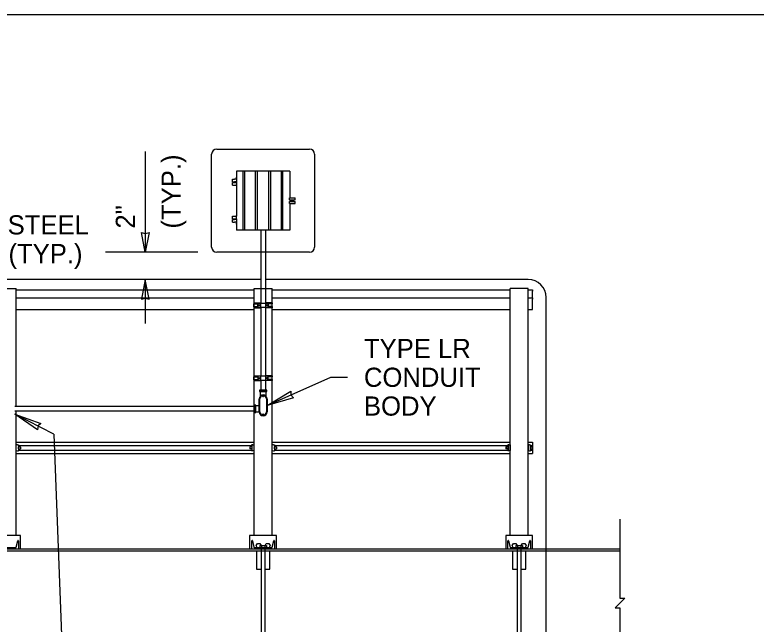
# Model space of a CAD drawing. Extents: x 99862 to 103680, y 99470 to 105076.
# Drawn here: x 101141 to 101760, y 101567 to 102076 of the extents above; entities that cross this region are included whole.
import ezdxf

# ---------------------------------------------------------------- set-up
doc = ezdxf.new("R2010")
doc.units = 0
for name, color, linetype in [('Level 1', 7, 'Continuous'), ('Level 10', 7, 'Continuous'), ('Level 12', 7, 'Continuous'), ('Level 15', 7, 'Continuous'), ('Level 16', 7, 'Continuous'), ('Level 18', 7, 'Continuous'), ('Level 19', 7, 'Continuous'), ('Level 2', 7, 'Continuous'), ('Level 20', 7, 'Continuous'), ('Level 27', 7, 'Continuous'), ('Level 4', 7, 'Continuous'), ('Level 5', 7, 'Continuous'), ('Level 9', 7, 'Continuous')]:
    doc.layers.add(name, color=color, linetype=linetype)

msp = doc.modelspace()

# ---------------------------------------------------------------- linework, layer by layer
at = {"layer": 'Level 1'}
for p, q in [((101346.66, 101854.73), (100923.17, 101854.73)), ((101569.75, 101854.73), (101350.49, 101854.73)), ((101584.75, 101329.97), (101584.75, 101839.73))]:
    msp.add_line(p, q, dxfattribs=at)
msp.add_lwpolyline([(99862, 99999.5), (103151, 99999.5), (103151, 102075.5), (99862, 102075.5)], close=True, dxfattribs=at)
msp.add_arc((101569.75, 101839.73), 15, 0, 90, dxfattribs=at)
at = {"layer": 'Level 10'}
for p, q in [((101146.16, 101641.07), (101123.67, 101641.07)), ((101146.16, 101629.82), (101146.16, 101641.07)), ((101337.33, 101641.07), (101337.33, 101629.82)), ((101359.82, 101641.07), (101337.33, 101641.07)), ((101359.82, 101629.82), (101359.82, 101641.07)), ((101551.02, 101641.07), (101551.02, 101629.82)), ((101573.51, 101641.07), (101551.02, 101641.07)), ((101573.51, 101629.82), (101573.51, 101641.07)), ((101142.55, 101631.42), (101143.73, 101636.65)), ((101144.29, 101636.58), (101144.29, 101629.82)), ((101339.21, 101629.82), (101339.21, 101636.58)), ((101339.76, 101636.65), (101340.94, 101631.42)), ((101356.21, 101631.42), (101357.39, 101636.65)), ((101357.95, 101636.58), (101357.95, 101629.82)), ((101552.89, 101629.82), (101552.89, 101636.58)), ((101553.44, 101636.65), (101554.63, 101631.42)), ((101569.89, 101631.42), (101571.08, 101636.65)), ((101571.63, 101636.58), (101571.63, 101629.82)), ((101144.29, 101629.82), (101125.55, 101629.82)), ((101127.81, 101630.99), (101142.02, 101630.99)), ((101357.95, 101629.82), (101339.21, 101629.82)), ((101341.47, 101630.99), (101355.68, 101630.99)), ((101571.63, 101629.82), (101552.89, 101629.82)), ((101555.16, 101630.99), (101569.36, 101630.99)), ((101349.98, 101612.95), (101354.2, 101612.95)), ((101563.67, 101612.95), (101567.88, 101612.95))]:
    msp.add_line(p, q, dxfattribs=at)
for points in [[(101347.17, 101627.95), (101342.95, 101627.95), (101342.95, 101612.95), (101347.17, 101612.95)], [(101354.2, 101612.95), (101354.2, 101627.95), (101349.98, 101627.95)], [(101560.85, 101627.95), (101556.64, 101627.95), (101556.64, 101612.95), (101560.85, 101612.95)], [(101567.88, 101612.95), (101567.88, 101627.95), (101563.67, 101627.95)]]:
    msp.add_lwpolyline(points, dxfattribs=at)
for centre, radius, start, end in [((101144.01, 101636.58), 0.281, 0, 167.26097), ((101339.49, 101636.58), 0.281, 12.73903, 180), ((101357.67, 101636.58), 0.281, 0, 167.26097), ((101553.17, 101636.58), 0.281, 12.73903, 180), ((101571.35, 101636.58), 0.281, 0, 167.26097), ((101142.02, 101631.54), 0.544, 270, 347.26097), ((101341.47, 101631.54), 0.544, 192.73903, 270), ((101355.68, 101631.54), 0.544, 270, 347.26097), ((101555.16, 101631.54), 0.544, 192.73903, 270), ((101569.36, 101631.54), 0.544, 270, 347.26097)]:
    msp.add_arc(centre, radius, start, end, dxfattribs=at)
at = {"layer": 'Level 12'}
for p, q in [((101646.35, 101629.82), (100274.6, 101629.82)), ((101646.35, 101627.95), (100276.47, 101627.95))]:
    msp.add_line(p, q, dxfattribs=at)
at = {"layer": 'Level 15'}
for p, q in [((101250.23, 101961.42), (101250.23, 101877.45)), ((101294.13, 101877.45), (101217.08, 101877.45)), ((101250.23, 101854.73), (101250.23, 101818.04)), ((101173.95, 101725.61), (101141.32, 101742.4))]:
    msp.add_line(p, q, dxfattribs=at)
for points in [[(101250.23, 101877.45), (101247.02, 101893.82), (101250.23, 101893.07), (101253.44, 101893.82)], [(101250.23, 101854.73), (101247.02, 101838.36), (101250.23, 101839.12), (101253.44, 101838.36)], [(101351.86, 101749.6), (101371.59, 101761.47), (101371.82, 101758.32), (101373.98, 101756)], [(101141.32, 101742.4), (101163.01, 101734.66), (101160.71, 101732.48), (101160.29, 101729.34)]]:
    msp.add_lwpolyline(points, close=True, dxfattribs=at)
for points in [[(101351.86, 101749.6), (101405, 101773.11), (101419, 101773.11)], [(101173.95, 101725.61), (101193.42, 101215.78), (101209.42, 101215.78)], [(101646.35, 101654.6), (101646.35, 101588.89), (101650.39, 101588.89), (101642.32, 101580.82), (101646.35, 101580.82), (101646.35, 101515.1)]]:
    msp.add_lwpolyline(points, dxfattribs=at)
at = {"layer": 'Level 16'}
for p, q in [((101309.88, 101963.43), (101387.27, 101963.43)), ((101305.59, 101881.75), (101305.59, 101959.13)), ((101391.57, 101959.13), (101391.57, 101881.75)), ((101387.27, 101877.45), (101309.88, 101877.45))]:
    msp.add_line(p, q, dxfattribs=at)
for centre, start, end in [((101309.88, 101959.13), 90, 180), ((101387.27, 101959.13), 0, 90), ((101309.88, 101881.75), 180, 270), ((101387.27, 101881.75), 270, 0)]:
    msp.add_arc(centre, 4.3, start, end, dxfattribs=at)
at = {"layer": 'Level 18'}
for p, q in [((101346.66, 101895.74), (101346.66, 101834.89)), ((101350.49, 101895.74), (101350.49, 101834.89)), ((101346.66, 101831.43), (101346.66, 101774.02)), ((101350.49, 101831.43), (101350.49, 101774.02)), ((101346.66, 101770.56), (101346.66, 101762.27)), ((101350.49, 101770.56), (101350.49, 101762.27)), ((101346.12, 101761.18), (101346.12, 101757.24)), ((101346.58, 101761.18), (101346.58, 101762.27)), ((101347.58, 101761.18), (101347.58, 101762.27)), ((101348.58, 101761.18), (101348.58, 101762.27)), ((101349.58, 101761.18), (101349.58, 101762.27)), ((101350.59, 101761.18), (101350.59, 101762.27)), ((101351.04, 101757.24), (101351.04, 101761.18)), ((101345.3, 101744.14), (101345.3, 101755.07)), ((101351.86, 101755.07), (101351.86, 101744.14)), ((101341.38, 101748.68), (101141.32, 101748.68)), ((101342.47, 101748.79), (101341.38, 101748.79)), ((101342.47, 101747.79), (101341.38, 101747.79)), ((101342.47, 101746.79), (101341.38, 101746.79)), ((101342.47, 101745.78), (101341.38, 101745.78)), ((101345.3, 101749.25), (101342.47, 101749.25)), ((101341.38, 101744.85), (101141.32, 101744.85)), ((101342.47, 101744.78), (101341.38, 101744.78)), ((101342.47, 101744.33), (101345.3, 101744.33))]:
    msp.add_line(p, q, dxfattribs=at)
for points in [[(101351.59, 101762.27), (101345.58, 101762.27), (101345.58, 101761.18), (101351.59, 101761.18)], [(101341.38, 101749.79), (101341.38, 101743.78), (101342.47, 101743.78), (101342.47, 101749.79)]]:
    msp.add_lwpolyline(points, close=True, dxfattribs=at)
for centre, start, end in [((101348.58, 101755.07), 0, 180), ((101348.58, 101744.14), 180, 0)]:
    msp.add_arc(centre, 3.28, start, end, dxfattribs=at)
at = {"layer": 'Level 19'}
for p, q in [((101142.44, 101846.04), (101341.08, 101846.04)), ((101356.07, 101846.04), (101554.74, 101846.04)), ((101569.73, 101846.04), (101573.51, 101846.04)), ((101573.51, 101846.04), (101573.51, 101844.93)), ((101573.51, 101839.5), (101573.51, 101844.93)), ((101142.44, 101839.5), (101341.08, 101839.5)), ((101356.07, 101839.5), (101554.74, 101839.5)), ((101569.73, 101839.5), (101573.51, 101839.5)), ((101573.51, 101839.5), (101573.51, 101838.34)), ((101573.51, 101829.67), (101573.51, 101838.34)), ((101142.44, 101829.67), (101341.08, 101829.67)), ((101356.07, 101829.67), (101554.74, 101829.67)), ((101569.73, 101829.67), (101573.51, 101829.67)), ((101143.48, 101716.86), (101142.41, 101716.69)), ((101142.44, 101718.86), (101341.08, 101718.86)), ((101143.48, 101716.86), (101144.15, 101716.86)), ((101144.15, 101716.86), (101144.48, 101716.86)), ((101144.23, 101715.03), (101144.23, 101713.53)), ((101144.23, 101715.03), (101145.73, 101715.03)), ((101144.48, 101716.86), (101144.48, 101715.03)), ((101144.48, 101716.86), (101144.5, 101716.86)), ((101144.53, 101716.04), (101339.01, 101716.04)), ((101145.73, 101715.03), (101145.94, 101715.03)), ((101145.94, 101714.92), (101145.94, 101715.03)), ((101145.94, 101714.92), (101145.94, 101713.53)), ((101337.55, 101715.03), (101337.55, 101714.92)), ((101337.76, 101715.03), (101337.55, 101715.03)), ((101337.55, 101714.92), (101337.55, 101713.53)), ((101339.26, 101715.03), (101337.76, 101715.03)), ((101339.01, 101716.86), (101339, 101716.86)), ((101339.01, 101716.86), (101339.01, 101715.03)), ((101339.35, 101716.86), (101339.01, 101716.86)), ((101339.26, 101715.03), (101339.26, 101713.53)), ((101340.01, 101716.86), (101339.35, 101716.86)), ((101340.01, 101716.86), (101341.08, 101716.69)), ((101356.07, 101718.86), (101554.74, 101718.86)), ((101357.14, 101716.86), (101356.07, 101716.69)), ((101357.14, 101716.86), (101357.81, 101716.86)), ((101357.81, 101716.86), (101358.14, 101716.86)), ((101357.89, 101715.03), (101357.89, 101713.53)), ((101357.89, 101715.03), (101359.39, 101715.03)), ((101358.14, 101716.86), (101358.14, 101715.03)), ((101358.14, 101716.86), (101358.16, 101716.86)), ((101358.14, 101716.04), (101552.69, 101716.04)), ((101359.39, 101715.03), (101359.6, 101715.03)), ((101359.6, 101714.92), (101359.6, 101715.03)), ((101359.6, 101714.92), (101359.6, 101713.53)), ((101551.45, 101715.03), (101551.23, 101715.03)), ((101551.23, 101714.92), (101551.23, 101713.53)), ((101551.24, 101715.03), (101551.24, 101714.92)), ((101551.45, 101715.03), (101551.45, 101713.53)), ((101552.95, 101715.03), (101551.45, 101715.03)), ((101552.69, 101716.86), (101552.68, 101716.86)), ((101552.69, 101716.86), (101552.69, 101715.03)), ((101553.03, 101716.86), (101552.69, 101716.86)), ((101552.95, 101715.03), (101552.95, 101713.53)), ((101553.03, 101716.86), (101553.03, 101711.71)), ((101553.69, 101716.86), (101553.03, 101716.86)), ((101553.69, 101716.86), (101554.77, 101716.69)), ((101554.77, 101716.69), (101554.77, 101711.88)), ((101569.73, 101718.86), (101573.51, 101718.86)), ((101569.75, 101716.69), (101569.73, 101716.69)), ((101570.83, 101716.86), (101569.75, 101716.69)), ((101569.75, 101716.69), (101569.75, 101711.88)), ((101570.83, 101716.86), (101571.49, 101716.86)), ((101571.49, 101716.86), (101571.49, 101711.71)), ((101571.49, 101716.86), (101571.83, 101716.86)), ((101571.57, 101715.03), (101573.07, 101715.03)), ((101571.57, 101715.03), (101571.57, 101713.53)), ((101571.83, 101716.86), (101571.84, 101716.86)), ((101571.83, 101716.86), (101571.83, 101715.03)), ((101571.83, 101716.04), (101573.51, 101716.04)), ((101573.07, 101715.03), (101573.29, 101715.03)), ((101573.07, 101715.03), (101573.07, 101713.53)), ((101573.28, 101714.92), (101573.28, 101715.03)), ((101573.28, 101714.92), (101573.51, 101714.92)), ((101573.29, 101714.92), (101573.29, 101713.53)), ((101573.51, 101718.86), (101573.51, 101716.04)), ((101573.51, 101716.04), (101573.51, 101714.92)), ((101573.51, 101714.92), (101573.51, 101713.42)), ((101142.41, 101711.88), (101143.48, 101711.71)), ((101142.44, 101709.48), (101341.08, 101709.48)), ((101143.48, 101711.71), (101144.15, 101711.71)), ((101144.15, 101711.71), (101144.48, 101711.71)), ((101144.23, 101713.53), (101145.73, 101713.53)), ((101144.48, 101713.53), (101144.48, 101711.71)), ((101144.48, 101711.71), (101144.5, 101711.71)), ((101144.53, 101712.3), (101339.01, 101712.3)), ((101145.73, 101713.53), (101145.94, 101713.53)), ((101337.76, 101713.53), (101337.55, 101713.53)), ((101339.26, 101713.53), (101337.76, 101713.53)), ((101339.01, 101711.71), (101339, 101711.71)), ((101339.01, 101713.53), (101339.01, 101711.71)), ((101339.35, 101711.71), (101339.01, 101711.71)), ((101340.01, 101711.71), (101339.35, 101711.71)), ((101341.08, 101711.88), (101340.01, 101711.71)), ((101356.07, 101711.88), (101357.14, 101711.71)), ((101356.07, 101709.48), (101554.74, 101709.48)), ((101357.14, 101711.71), (101357.81, 101711.71)), ((101357.81, 101711.71), (101358.14, 101711.71)), ((101357.89, 101713.53), (101359.39, 101713.53)), ((101358.14, 101713.53), (101358.14, 101711.71)), ((101358.14, 101712.3), (101552.69, 101712.3)), ((101358.14, 101711.71), (101358.16, 101711.71)), ((101359.39, 101713.53), (101359.6, 101713.53)), ((101551.45, 101713.53), (101551.23, 101713.53)), ((101552.95, 101713.53), (101551.45, 101713.53)), ((101552.69, 101711.71), (101552.68, 101711.71)), ((101552.69, 101713.53), (101552.69, 101711.71)), ((101553.03, 101711.71), (101552.69, 101711.71)), ((101553.69, 101711.71), (101553.03, 101711.71)), ((101554.77, 101711.88), (101553.69, 101711.71)), ((101569.73, 101711.88), (101569.75, 101711.88)), ((101569.73, 101709.48), (101573.51, 101709.48)), ((101569.75, 101711.88), (101570.83, 101711.71)), ((101570.83, 101711.71), (101571.49, 101711.71)), ((101571.49, 101711.71), (101571.83, 101711.71)), ((101571.57, 101713.53), (101573.07, 101713.53)), ((101571.83, 101713.53), (101571.83, 101711.71)), ((101571.83, 101713.42), (101573.51, 101713.42)), ((101571.83, 101712.3), (101573.51, 101712.3)), ((101571.83, 101711.71), (101571.84, 101711.71)), ((101573.07, 101713.53), (101573.29, 101713.53)), ((101573.51, 101713.42), (101573.51, 101712.3)), ((101573.51, 101712.3), (101573.51, 101709.48))]:
    msp.add_line(p, q, dxfattribs=at)
at = {"layer": 'Level 2'}
for p, q in [((101326.37, 101945.14), (101326.37, 101938.31)), ((101370.78, 101945.14), (101326.37, 101945.14)), ((101370.78, 101945.14), (101370.78, 101922.72)), ((101322.96, 101936.04), (101322.96, 101938.31)), ((101322.96, 101938.31), (101324.66, 101938.31)), ((101326.66, 101938.31), (101324.66, 101938.31)), ((101326.37, 101938.31), (101326.37, 101940.01)), ((101326.66, 101936.04), (101326.66, 101938.31)), ((101322.96, 101936.04), (101324.66, 101936.04)), ((101322.97, 101935.62), (101325.89, 101935.62)), ((101322.97, 101933.35), (101322.97, 101935.62)), ((101322.97, 101933.35), (101325.89, 101933.35)), ((101326.66, 101936.04), (101324.66, 101936.04)), ((101326.45, 101935.62), (101325.89, 101935.62)), ((101326.45, 101933.35), (101325.89, 101933.35)), ((101326.37, 101936.04), (101326.37, 101935.62)), ((101326.37, 101933.35), (101326.37, 101907.54)), ((101326.45, 101935.62), (101326.45, 101933.35)), ((101370.5, 101922.72), (101375.35, 101922.72)), ((101370.5, 101921.19), (101370.5, 101922.72)), ((101370.5, 101921.19), (101375.35, 101921.19)), ((101370.5, 101919.69), (101375.35, 101919.69)), ((101370.5, 101918.15), (101370.5, 101919.69)), ((101370.5, 101918.15), (101375.35, 101918.15)), ((101370.78, 101921.19), (101370.78, 101919.69)), ((101370.78, 101918.15), (101370.78, 101895.74)), ((101373.2, 101919.69), (101375.34, 101919.69)), ((101375.34, 101919.69), (101375.34, 101919.69)), ((101375.35, 101921.19), (101375.35, 101922.72)), ((101375.35, 101918.15), (101375.35, 101919.69)), ((101322.97, 101905.26), (101322.97, 101907.54)), ((101322.97, 101907.54), (101325.89, 101907.54)), ((101326.45, 101907.54), (101325.89, 101907.54)), ((101326.45, 101905.26), (101326.45, 101907.54)), ((101322.96, 101904.85), (101324.66, 101904.85)), ((101322.96, 101902.57), (101322.96, 101904.85)), ((101322.96, 101902.57), (101324.66, 101902.57)), ((101322.97, 101905.26), (101325.89, 101905.26)), ((101326.66, 101904.85), (101324.66, 101904.85)), ((101326.66, 101902.57), (101324.66, 101902.57)), ((101326.45, 101905.26), (101325.89, 101905.26)), ((101326.37, 101905.26), (101326.37, 101904.85)), ((101326.37, 101900.87), (101326.37, 101902.57)), ((101326.37, 101902.57), (101326.37, 101895.74)), ((101326.66, 101902.57), (101326.66, 101904.85)), ((101346.66, 101895.74), (101326.37, 101895.74)), ((101350.49, 101895.74), (101346.66, 101895.74)), ((101370.78, 101895.74), (101350.49, 101895.74)), ((101127.42, 101847.23), (101142.41, 101847.23)), ((101142.41, 101748.68), (101142.41, 101847.23)), ((101341.08, 101641.07), (101341.08, 101847.23)), ((101341.08, 101847.23), (101356.07, 101847.23)), ((101356.07, 101641.07), (101356.07, 101847.23)), ((101554.74, 101641.07), (101554.74, 101847.23)), ((101569.73, 101641.07), (101569.73, 101847.23)), ((101142.41, 101641.07), (101142.41, 101744.85))]:
    msp.add_line(p, q, dxfattribs=at)
for centre, start, end in [((101330.93, 101940.01), 179.99988, 180), ((101330.93, 101900.87), 180, 180.00012)]:
    msp.add_arc(centre, 4.56, start, end, dxfattribs=at)
msp.add_open_spline([(101569.73, 101847.23), (101562.24, 101847.23), (101554.74, 101847.23)], degree=2, dxfattribs=at)
at = {"layer": 'Level 27'}
for p, q in [((101332.04, 101895.74), (101332.04, 101945.14)), ((101333.37, 101895.74), (101333.37, 101945.14)), ((101342.2, 101895.74), (101342.2, 101945.14)), ((101343.9, 101895.74), (101343.9, 101945.14)), ((101353.26, 101895.74), (101353.26, 101945.14)), ((101354.95, 101895.74), (101354.95, 101945.14)), ((101363.78, 101895.74), (101363.78, 101945.14)), ((101365.12, 101895.74), (101365.12, 101945.14))]:
    msp.add_line(p, q, dxfattribs=at)
at = {"layer": 'Level 4'}
for p, q in [((101324.08, 101935.62), (101324.08, 101936.04)), ((101325.22, 101935.62), (101325.22, 101936.04)), ((101373.65, 101920.86), (101371.62, 101920.86)), ((101371.62, 101920.02), (101373.65, 101920.02)), ((101372.08, 101921.19), (101372.08, 101920.86)), ((101372.08, 101920.02), (101372.08, 101919.69)), ((101373.2, 101921.19), (101373.2, 101920.86)), ((101373.2, 101920.02), (101373.2, 101919.69)), ((101324.08, 101904.85), (101324.08, 101905.26)), ((101325.22, 101904.85), (101325.22, 101905.26))]:
    msp.add_line(p, q, dxfattribs=at)
for centre, radius, start, end in [((101371.62, 101920.44), 0.423, 90, 270), ((101372.64, 101920.45), 1.26, 322.93354, 342.1249), ((101373.65, 101920.44), 0.423, 270, 90), ((101372.64, 101920.45), 1.26, 17.14533, 36.16205)]:
    msp.add_arc(centre, radius, start, end, dxfattribs=at)
at = {"layer": 'Level 5'}
for p, q in [((101341.08, 101835.16), (101346.66, 101835.16)), ((101341.08, 101835.16), (101341.08, 101834.24)), ((101341.08, 101834.24), (101344.23, 101834.24)), ((101341.08, 101832.08), (101344.23, 101832.08)), ((101341.08, 101832.08), (101341.08, 101831.15)), ((101346.45, 101834.89), (101346.45, 101831.43)), ((101356.07, 101835.16), (101350.49, 101835.16)), ((101350.61, 101834.89), (101350.61, 101831.43)), ((101356.07, 101834.24), (101352.84, 101834.24)), ((101356.07, 101832.08), (101352.84, 101832.08)), ((101356.07, 101835.16), (101356.07, 101834.24)), ((101356.07, 101832.08), (101356.07, 101831.15)), ((101341.08, 101831.15), (101346.66, 101831.15)), ((101356.07, 101831.15), (101350.49, 101831.15)), ((101341.08, 101774.29), (101341.08, 101773.37)), ((101341.08, 101774.29), (101346.66, 101774.29)), ((101341.08, 101773.37), (101344.27, 101773.37)), ((101341.08, 101771.21), (101341.08, 101770.28)), ((101341.08, 101771.21), (101344.27, 101771.21)), ((101341.08, 101770.28), (101346.66, 101770.28)), ((101346.5, 101774.02), (101346.5, 101770.56)), ((101356.07, 101774.29), (101350.49, 101774.29)), ((101356.07, 101770.28), (101350.49, 101770.28)), ((101350.66, 101774.02), (101350.66, 101770.56)), ((101356.07, 101773.37), (101352.88, 101773.37)), ((101356.07, 101771.21), (101352.88, 101771.21)), ((101356.07, 101774.29), (101356.07, 101773.37)), ((101356.07, 101771.21), (101356.07, 101770.28))]:
    msp.add_line(p, q, dxfattribs=at)
for points in [[(101341.08, 101831.92), (101340.93, 101831.92), (101340.93, 101834.39), (101341.08, 101834.39)], [(101356.07, 101831.92), (101356.23, 101831.92), (101356.23, 101834.39), (101356.07, 101834.39)], [(101341.08, 101771.05), (101340.93, 101771.05), (101340.93, 101773.52), (101341.08, 101773.52)], [(101356.07, 101771.05), (101356.23, 101771.05), (101356.23, 101773.52), (101356.07, 101773.52)]]:
    msp.add_lwpolyline(points, dxfattribs=at)
for points in [[(101352.84, 101834.89), (101352.84, 101831.43), (101344.23, 101831.43), (101344.23, 101834.89)], [(101345.03, 101833.5), (101345.34, 101833.32), (101345.34, 101832.97), (101345.03, 101832.8), (101344.73, 101832.97), (101344.73, 101833.32)], [(101352.04, 101833.5), (101352.35, 101833.32), (101352.35, 101832.97), (101352.04, 101832.8), (101351.74, 101832.97), (101351.74, 101833.32)], [(101344.27, 101774.02), (101344.27, 101770.56), (101352.88, 101770.56), (101352.88, 101774.02)], [(101345.07, 101772.63), (101344.76, 101772.45), (101344.76, 101772.1), (101345.07, 101771.93), (101345.37, 101772.1), (101345.37, 101772.45)], [(101352.08, 101772.63), (101351.77, 101772.45), (101351.77, 101772.1), (101352.08, 101771.93), (101352.38, 101772.1), (101352.38, 101772.45)]]:
    msp.add_lwpolyline(points, close=True, dxfattribs=at)
for centre in [(101345.03, 101833.15), (101352.04, 101833.15), (101345.07, 101772.28), (101352.08, 101772.28)]:
    msp.add_circle(centre, 0.552, dxfattribs=at)
at = {"layer": 'Level 9'}
for p, q in [((101345.85, 101744.14), (101345.85, 101755.07)), ((101351.31, 101755.07), (101351.31, 101744.14)), ((101342.66, 101632.63), (101343.75, 101634.51)), ((101343.75, 101634.51), (101345.91, 101634.51)), ((101345.91, 101634.51), (101346.86, 101632.87)), ((101350.3, 101632.87), (101351.24, 101634.51)), ((101351.24, 101634.51), (101353.41, 101634.51)), ((101353.41, 101634.51), (101354.49, 101632.63)), ((101556.35, 101632.63), (101557.43, 101634.51)), ((101557.43, 101634.51), (101559.59, 101634.51)), ((101559.59, 101634.51), (101560.54, 101632.87)), ((101563.98, 101632.87), (101564.93, 101634.51)), ((101564.93, 101634.51), (101567.09, 101634.51)), ((101567.09, 101634.51), (101568.17, 101632.63)), ((101343.61, 101630.99), (101342.66, 101632.63)), ((101345.87, 101632.87), (101347.22, 101632.87)), ((101345.87, 101632.87), (101345.87, 101630.99)), ((101347.17, 101539.86), (101347.17, 101629.82)), ((101347.22, 101632.87), (101347.22, 101630.99)), ((101347.22, 101632.87), (101349.93, 101632.87)), ((101349.93, 101632.87), (101351.28, 101632.87)), ((101349.93, 101632.87), (101349.93, 101630.99)), ((101349.98, 101629.82), (101349.98, 101539.86)), ((101351.28, 101632.87), (101351.28, 101630.99)), ((101354.49, 101632.63), (101353.54, 101630.99)), ((101557.29, 101630.99), (101556.35, 101632.63)), ((101559.56, 101632.87), (101560.91, 101632.87)), ((101559.56, 101632.87), (101559.56, 101630.99)), ((101560.85, 101539.86), (101560.85, 101629.82)), ((101560.91, 101632.87), (101563.61, 101632.87)), ((101560.91, 101632.87), (101560.91, 101630.99)), ((101563.61, 101632.87), (101564.97, 101632.87)), ((101563.61, 101632.87), (101563.61, 101630.99)), ((101563.67, 101629.82), (101563.67, 101539.86)), ((101564.97, 101632.87), (101564.97, 101630.99)), ((101568.17, 101632.63), (101567.23, 101630.99))]:
    msp.add_line(p, q, dxfattribs=at)
for centre in [(101348.58, 101757.26), (101348.58, 101741.95)]:
    msp.add_circle(centre, 0.547, dxfattribs=at)
for centre, start, end in [((101348.58, 101755.07), 0, 180), ((101348.58, 101744.14), 180, 0)]:
    msp.add_arc(centre, 2.73, start, end, dxfattribs=at)

# ---------------------------------------------------------------- texts
at = {"layer": 'Level 20'}
for s, p in [('(TYP.)', (101279.79, 101897.17)), ('2"', (101241.57, 101897.17))]:
    msp.add_text(s, height=16, rotation=90, dxfattribs=at).set_placement(p)
for s, p in [('1 1/2" (IN) STEEL', (101032.62, 101892.28)), ('CONDUIT (TYP.)', (101032.62, 101868.28)), ('TYPE LR', (101432.73, 101789.11)), ('CONDUIT', (101432.73, 101765.11)), ('BODY', (101432.73, 101741.11))]:
    msp.add_text(s, height=16, dxfattribs=at).set_placement(p)

doc.saveas('drawing.dxf')
